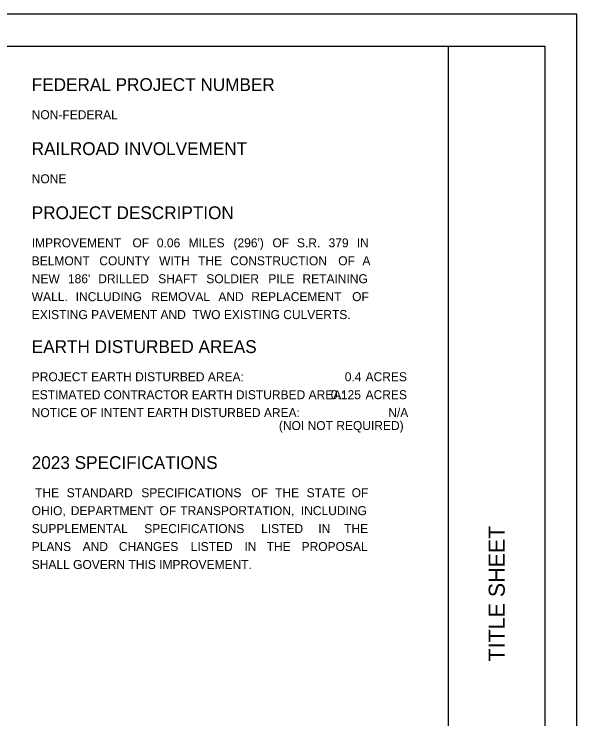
# Model space of a CAD drawing. Extents: x 0 to 2329303, y 0 to 694397.
# Drawn here: x 25.23 to 34, y 11 to 22 of the extents above; entities that cross this region are included whole.
import ezdxf

# ---------------------------------------------------------------- set-up
doc = ezdxf.new("R2010")
doc.units = 0
for name, color, linetype in [('SH_Border', 7, 'Continuous'), ('SH_Cut_Line', 7, 'Continuous'), ('SH_Data', 7, 'Continuous')]:
    doc.layers.add(name, color=color, linetype=linetype)

msp = doc.modelspace()

# ---------------------------------------------------------------- linework, layer by layer
at = {"layer": 'SH_Border'}
msp.add_line((32, 0.5), (32, 21.5), dxfattribs=at)
msp.add_lwpolyline([(1.5, 21.5), (33.5, 21.5), (33.5, 0.5), (1.5, 0.5)], close=True, dxfattribs=at)
at = {"layer": 'SH_Cut_Line'}
msp.add_lwpolyline([(0, 0), (34, 0), (34, 22), (0, 22)], close=True, dxfattribs=at)

# ---------------------------------------------------------------- texts
at = {"layer": 'SH_Data'}
for s, height, p in [('FEDERAL PROJECT NUMBER', 0.2, (25.5, 20.8)), ('NON-FEDERAL', 0.14, (25.5, 20.36)), ('RAILROAD INVOLVEMENT', 0.2, (25.5, 19.8)), ('NONE', 0.14, (25.5, 19.36)), ('PROJECT DESCRIPTION', 0.2, (25.5, 18.8)), ('IMPROVEMENT ', 0.14, (25.5, 18.36)), ('OF ', 0.14, (27.07, 18.36)), ('0.06 ', 0.14, (27.451, 18.36)), ('MILES ', 0.14, (27.945, 18.36)), ("(296') ", 0.14, (28.646, 18.36)), ('OF ', 0.14, (29.253, 18.36)), ('S.R. ', 0.14, (29.635, 18.36)), ('379 ', 0.14, (30.128, 18.36)), ('IN ', 0.14, (30.568, 18.36)), ('BELMONT ', 0.14, (25.5, 18.08)), ('COUNTY ', 0.14, (26.554, 18.08)), ('WITH ', 0.14, (27.486, 18.08)), ('THE ', 0.14, (28.094, 18.08)), ('CONSTRUCTION ', 0.14, (28.595, 18.08)), ('OF ', 0.14, (30.279, 18.08)), ('A ', 0.14, (30.656, 18.08)), ('NEW ', 0.14, (25.5, 17.8)), ("186' ", 0.14, (26.065, 17.8)), ('DRILLED ', 0.14, (26.537, 17.8)), ('SHAFT ', 0.14, (27.472, 17.8)), ('SOLDIER ', 0.14, (28.222, 17.8)), ('PILE ', 0.14, (29.189, 17.8)), ('RETAINING ', 0.14, (29.721, 17.8)), ('WALL. ', 0.14, (25.5, 17.52)), ('INCLUDING ', 0.14, (26.186, 17.52)), ('REMOVAL ', 0.14, (27.365, 17.52)), ('AND ', 0.14, (28.41, 17.52)), ('REPLACEMENT ', 0.14, (28.925, 17.52)), ('OF ', 0.14, (30.496, 17.52)), ('EXISTING PAVEMENT AND  TWO EXISTING CULVERTS.', 0.14, (25.5, 17.24)), ('EARTH DISTURBED AREAS', 0.2, (25.5, 16.71)), ('PROJECT EARTH DISTURBED AREA:', 0.14, (25.5, 16.27)), ('0.4', 0.14, (30.381, 16.27)), (' ACRES', 0.14, (30.653, 16.27)), ('ESTIMATED CONTRACTOR EARTH DISTURBED AREA:', 0.14, (25.5, 15.99)), ('0.125', 0.14, (30.164, 15.99)), (' ACRES', 0.14, (30.653, 15.99)), ('NOTICE OF INTENT EARTH DISTURBED AREA:', 0.14, (25.5, 15.71)), ('N/A ', 0.14, (31.059, 15.71)), ('(NOI NOT REQUIRED)', 0.14, (29.354, 15.508)), ('2023 SPECIFICATIONS', 0.2, (25.5, 14.9)), (' THE ', 0.14, (25.5, 14.46)), ('STANDARD ', 0.14, (26.046, 14.46)), ('SPECIFICATIONS ', 0.14, (27.209, 14.46)), ('OF ', 0.14, (28.925, 14.46)), ('THE ', 0.14, (29.294, 14.46)), ('STATE ', 0.14, (29.786, 14.46)), ('OF ', 0.14, (30.488, 14.46)), ('OHIO, ', 0.14, (25.5, 14.18)), ('DEPARTMENT ', 0.14, (26.109, 14.18)), ('OF ', 0.14, (27.493, 14.18)), ('TRANSPORTATION, ', 0.14, (27.816, 14.18)), ('INCLUDING ', 0.14, (29.696, 14.18)), ('SUPPLEMENTAL ', 0.14, (25.5, 13.9)), ('SPECIFICATIONS ', 0.14, (27.254, 13.9)), ('LISTED ', 0.14, (29.076, 13.9)), ('IN ', 0.14, (29.968, 13.9)), ('THE ', 0.14, (30.37, 13.9)), ('PLANS ', 0.14, (25.5, 13.62)), ('AND ', 0.14, (26.294, 13.62)), ('CHANGES ', 0.14, (26.859, 13.62)), ('LISTED ', 0.14, (27.979, 13.62)), ('IN ', 0.14, (28.816, 13.62)), ('THE ', 0.14, (29.163, 13.62)), ('PROPOSAL ', 0.14, (29.707, 13.62)), ('SHALL GOVERN THIS IMPROVEMENT.', 0.14, (25.5, 13.34))]:
    msp.add_text(s, height=height, dxfattribs=at).set_placement(p)
msp.add_text('TITLE SHEET', height=0.25, rotation=90, dxfattribs=at).set_placement((32.875, 11.897))

doc.saveas('drawing.dxf')
